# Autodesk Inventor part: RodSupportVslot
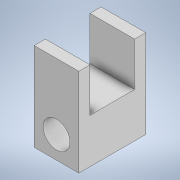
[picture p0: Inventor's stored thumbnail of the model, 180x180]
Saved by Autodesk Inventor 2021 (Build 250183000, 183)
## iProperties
Created: 2026-10
Part Number: RodSupportVslot
Material: Generic
Document SubType Name: Modeling
Designer: hp
Density: 1 g/cm^3
Appearance: Default
Author: hp
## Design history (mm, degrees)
sketch "Sketch1"
  geometry: L1 (10, -10)-(-10, -10); L2 (-10, -10)-(-10, 10); L3 (-10, 10)-(10, 10); L4 (10, 10)-(10, -10); L5 (10, -10)-(-10, 10); L6 (-10, -10)-(10, 10); L7 (-10, 10)-(10, 10); L8 (10, 10)-(10, 29.559); L9 (10, 29.559)-(-10, 29.559); L10 (-10, 29.559)-(-10, 10); C1 r 6 at (0, 0); 3 further points
  constraints: 20 end point, 4 parallel, 2 horizontal, 2 midpoint, 2 perpendicular, 1 centre point, 1 coincident
  dimensions: "d39" = 12 diameter of C1; "d40" = 20 distance of L2.end L3.end; "d41" = 20 distance of L1.end L2.end; "d42" = 20 distance of L9.end L8.end
extrude "Extrusion3" new body sketch "Sketch1" stored distance "d44" = 30; taper "d45" = 0 deg
extrude "Extrusion4" cut sketch "Sketch1" stored distance "d46" = 20; taper "d47" = 0 deg
body "Solid2"
